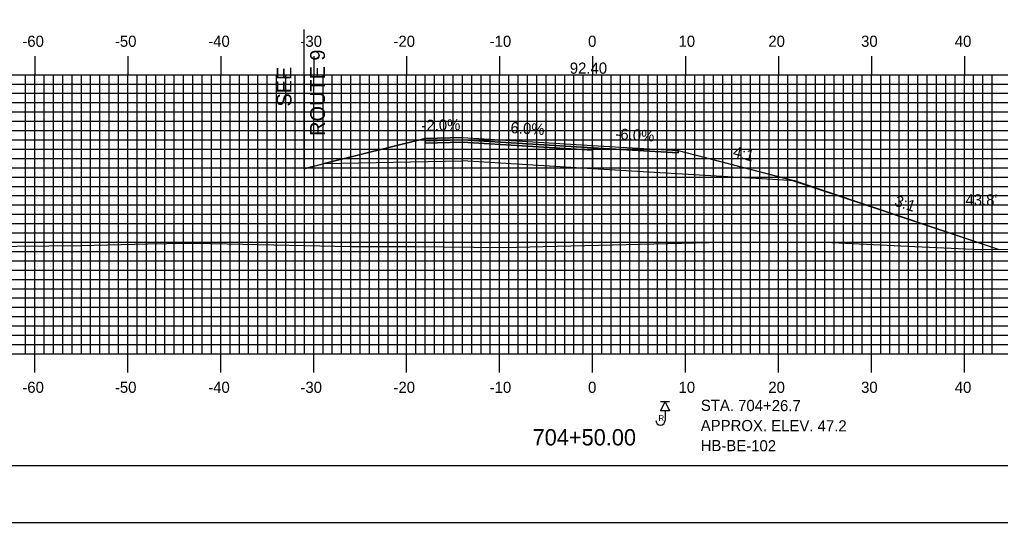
# Model space of a CAD drawing. Extents: x 853723 to 854066, y 364366 to 364586.
# Drawn here: x 853827.1 to 853932.6, y 364365.7 to 364419.7 of the extents above; entities that cross this region are included whole.
import ezdxf

# ---------------------------------------------------------------- set-up
doc = ezdxf.new("R2010")
doc.units = 0
for name, color, linetype in [('ANNOTATION', 7, 'Continuous'), ('BORDER', 7, 'Continuous'), ('BORING - REFUSAL', 7, 'Continuous'), ('D_Roadway_Centerline', 7, 'Continuous'), ('D_Roadway_Centerline_Text', 7, 'Continuous'), ('D_Roadway_Edge_Shoulder', 7, 'Continuous'), ('D_Roadway_Edge_TW', 7, 'Continuous'), ('D_Roadway_Pavement', 7, 'Continuous'), ('D_Roadway_SlopeLines', 7, 'Continuous'), ('D_Roadway_SubGrade', 7, 'Continuous'), ('D_Text_Standard', 7, 'Continuous'), ('H_V ANNOTATION', 7, 'Continuous'), ('MAJOR', 7, 'Continuous'), ('MINOR', 7, 'Continuous'), ('PLOT BOUNDARY', 7, 'Continuous'), ('S_Roadway_Centerline', 7, 'Continuous')]:
    doc.layers.add(name, color=color, linetype=linetype)

msp = doc.modelspace()

# ---------------------------------------------------------------- linework, layer by layer
at = {"layer": 'BORDER'}
msp.add_lwpolyline([(853739.12, 364371.79), (854059.12, 364371.79), (854059.12, 364581.79), (853739.12, 364581.79)], close=True, dxfattribs=at)
at = {"layer": 'BORING - REFUSAL'}
for p, q in [((853897, 364378.63), (853896.04, 364378.63)), ((853896.52, 364377.67), (853896.52, 364376.61))]:
    msp.add_line(p, q, dxfattribs=at)
msp.add_lwpolyline([(853896.52, 364378.63), (853897, 364377.67), (853896.04, 364377.67)], close=True, dxfattribs=at)
msp.add_arc((853896.03, 364376.61), 0.485, 180, 0, dxfattribs=at)
at = {"layer": 'D_Roadway_Centerline'}
msp.add_lwpolyline([(853857.67, 364403.69), (853859.85, 364404.23), (853870.72, 364406.95), (853874.72, 364407.03), (853888.72, 364406.19), (853897.92, 364405.64), (853909.92, 364402.54), (853910.52, 364402.38), (853932.48, 364395.02)], dxfattribs=at)
at = {"layer": 'D_Roadway_Edge_Shoulder'}
for points in [[(853874.72, 364407.03), (853870.72, 364406.95), (853870.72, 364406.7), (853874.72, 364406.78)], [(853888.72, 364406.19), (853897.92, 364405.64), (853897.92, 364405.39), (853888.72, 364405.94)]]:
    msp.add_lwpolyline(points, close=True, dxfattribs=at)
at = {"layer": 'D_Roadway_Edge_TW'}
msp.add_lwpolyline([(853874.72, 364407.03), (853888.72, 364406.19), (853888.72, 364405.94), (853874.72, 364406.78)], close=True, dxfattribs=at)
at = {"layer": 'D_Roadway_Pavement'}
for points in [[(853874.72, 364406.78), (853870.72, 364406.7), (853870.72, 364406.45), (853874.72, 364406.53)], [(853874.72, 364406.78), (853888.72, 364405.94), (853888.72, 364405.69), (853874.72, 364406.53)]]:
    msp.add_lwpolyline(points, close=True, dxfattribs=at)
msp.add_lwpolyline([(853888.72, 364405.94), (853888.72, 364405.69)], dxfattribs=at)
msp.add_lwpolyline([(853888.72, 364405.94), (853888.72, 364405.69)], dxfattribs=at)
at = {"layer": 'D_Roadway_SlopeLines'}
for points in [[(853870.72, 364406.95), (853857.67, 364403.69)], [(853897.92, 364405.64), (853909.92, 364402.54), (853932.48, 364395.02)]]:
    msp.add_lwpolyline(points, dxfattribs=at)
at = {"layer": 'D_Roadway_SubGrade'}
msp.add_line((853857.67, 364418.64), (853857.67, 364403.69), dxfattribs=at)
for points in [[(853874.72, 364406.53), (853870.72, 364406.45), (853870.72, 364406.7), (853870.72, 364406.95), (853859.85, 364404.23), (853874.72, 364404.53)], [(853874.72, 364406.53), (853888.72, 364405.69), (853888.72, 364403.69), (853874.72, 364404.53)], [(853888.72, 364405.69), (853888.72, 364405.94), (853897.92, 364405.39), (853897.92, 364405.64), (853910.52, 364402.38), (853888.72, 364403.69)]]:
    msp.add_lwpolyline(points, close=True, dxfattribs=at)
at = {"layer": 'MAJOR'}
for p, q in [((853828.72, 364415.79), (853828.72, 364413.79)), ((853838.72, 364415.79), (853838.72, 364413.79)), ((853848.72, 364415.79), (853848.72, 364413.79)), ((853858.72, 364415.79), (853858.72, 364413.79)), ((853868.72, 364415.79), (853868.72, 364413.79)), ((853878.72, 364415.79), (853878.72, 364413.79)), ((853888.72, 364415.79), (853888.72, 364413.79)), ((853898.72, 364415.79), (853898.72, 364413.79)), ((853908.72, 364415.79), (853908.72, 364413.79)), ((853918.72, 364415.79), (853918.72, 364413.79)), ((853928.72, 364415.79), (853928.72, 364413.79)), ((853748.72, 364413.79), (854028.72, 364413.79)), ((853748.72, 364413.79), (854028.72, 364413.79)), ((853828.72, 364383.79), (853828.72, 364413.79)), ((853838.72, 364383.79), (853838.72, 364413.79)), ((853848.72, 364383.79), (853848.72, 364413.79)), ((853858.72, 364383.79), (853858.72, 364413.79)), ((853868.72, 364383.79), (853868.72, 364413.79)), ((853878.72, 364383.79), (853878.72, 364413.79)), ((853888.72, 364383.79), (853888.72, 364413.79)), ((853898.72, 364383.79), (853898.72, 364413.79)), ((853908.72, 364383.79), (853908.72, 364413.79)), ((853918.72, 364383.79), (853918.72, 364413.79)), ((853928.72, 364383.79), (853928.72, 364413.79)), ((853748.72, 364408.79), (854028.72, 364408.79)), ((853748.72, 364403.79), (854028.72, 364403.79)), ((853748.72, 364398.79), (854028.72, 364398.79)), ((853748.72, 364393.79), (854028.72, 364393.79)), ((853748.72, 364388.79), (854028.72, 364388.79)), ((853748.72, 364383.79), (854028.72, 364383.79)), ((853748.72, 364383.79), (854028.72, 364383.79)), ((853828.72, 364381.78), (853828.72, 364383.79)), ((853838.72, 364381.78), (853838.72, 364383.79)), ((853848.72, 364381.78), (853848.72, 364383.79)), ((853858.72, 364381.78), (853858.72, 364383.79)), ((853868.72, 364381.78), (853868.72, 364383.79)), ((853878.72, 364381.78), (853878.72, 364383.79)), ((853888.72, 364381.78), (853888.72, 364383.79)), ((853898.72, 364381.78), (853898.72, 364383.79)), ((853908.72, 364381.78), (853908.72, 364383.79)), ((853918.72, 364381.78), (853918.72, 364383.79)), ((853928.72, 364381.78), (853928.72, 364383.79))]:
    msp.add_line(p, q, dxfattribs=at)
at = {"layer": 'MINOR'}
for p, q in [((853827.72, 364383.79), (853827.72, 364413.79)), ((853829.72, 364383.79), (853829.72, 364413.79)), ((853830.72, 364383.79), (853830.72, 364413.79)), ((853831.72, 364383.79), (853831.72, 364413.79)), ((853832.72, 364383.79), (853832.72, 364413.79)), ((853833.72, 364383.79), (853833.72, 364413.79)), ((853834.72, 364383.79), (853834.72, 364413.79)), ((853835.72, 364383.79), (853835.72, 364413.79)), ((853836.72, 364383.79), (853836.72, 364413.79)), ((853837.72, 364383.79), (853837.72, 364413.79)), ((853839.72, 364383.79), (853839.72, 364413.79)), ((853840.72, 364383.79), (853840.72, 364413.79)), ((853841.72, 364383.79), (853841.72, 364413.79)), ((853842.72, 364383.79), (853842.72, 364413.79)), ((853843.72, 364383.79), (853843.72, 364413.79)), ((853844.72, 364383.79), (853844.72, 364413.79)), ((853845.72, 364383.79), (853845.72, 364413.79)), ((853846.72, 364383.79), (853846.72, 364413.79)), ((853847.72, 364383.79), (853847.72, 364413.79)), ((853849.72, 364383.79), (853849.72, 364413.79)), ((853850.72, 364383.79), (853850.72, 364413.79)), ((853851.72, 364383.79), (853851.72, 364413.79)), ((853852.72, 364383.79), (853852.72, 364413.79)), ((853853.72, 364383.79), (853853.72, 364413.79)), ((853854.72, 364383.79), (853854.72, 364413.79)), ((853855.72, 364383.79), (853855.72, 364413.79)), ((853856.72, 364383.79), (853856.72, 364413.79)), ((853857.72, 364383.79), (853857.72, 364413.79)), ((853859.72, 364383.79), (853859.72, 364413.79)), ((853860.72, 364383.79), (853860.72, 364413.79)), ((853861.72, 364383.79), (853861.72, 364413.79)), ((853862.72, 364383.79), (853862.72, 364413.79)), ((853863.72, 364383.79), (853863.72, 364413.79)), ((853864.72, 364383.79), (853864.72, 364413.79)), ((853865.72, 364383.79), (853865.72, 364413.79)), ((853866.72, 364383.79), (853866.72, 364413.79)), ((853867.72, 364383.79), (853867.72, 364413.79)), ((853869.72, 364383.79), (853869.72, 364413.79)), ((853870.72, 364383.79), (853870.72, 364413.79)), ((853871.72, 364383.79), (853871.72, 364413.79)), ((853872.72, 364383.79), (853872.72, 364413.79)), ((853873.72, 364383.79), (853873.72, 364413.79)), ((853874.72, 364383.79), (853874.72, 364413.79)), ((853875.72, 364383.79), (853875.72, 364413.79)), ((853876.72, 364383.79), (853876.72, 364413.79)), ((853877.72, 364383.79), (853877.72, 364413.79)), ((853879.72, 364383.79), (853879.72, 364413.79)), ((853880.72, 364383.79), (853880.72, 364413.79)), ((853881.72, 364383.79), (853881.72, 364413.79)), ((853882.72, 364383.79), (853882.72, 364413.79)), ((853883.72, 364383.79), (853883.72, 364413.79)), ((853884.72, 364383.79), (853884.72, 364413.79)), ((853885.72, 364383.79), (853885.72, 364413.79)), ((853886.72, 364383.79), (853886.72, 364413.79)), ((853887.72, 364383.79), (853887.72, 364413.79)), ((853889.72, 364383.79), (853889.72, 364413.79)), ((853890.72, 364383.79), (853890.72, 364413.79)), ((853891.72, 364383.79), (853891.72, 364413.79)), ((853892.72, 364383.79), (853892.72, 364413.79)), ((853893.72, 364383.79), (853893.72, 364413.79)), ((853894.72, 364383.79), (853894.72, 364413.79)), ((853895.72, 364383.79), (853895.72, 364413.79)), ((853896.72, 364383.79), (853896.72, 364413.79)), ((853897.72, 364383.79), (853897.72, 364413.79)), ((853899.72, 364383.79), (853899.72, 364413.79)), ((853900.72, 364383.79), (853900.72, 364413.79)), ((853901.72, 364383.79), (853901.72, 364413.79)), ((853902.72, 364383.79), (853902.72, 364413.79)), ((853903.72, 364383.79), (853903.72, 364413.79)), ((853904.72, 364383.79), (853904.72, 364413.79)), ((853905.72, 364383.79), (853905.72, 364413.79)), ((853906.72, 364383.79), (853906.72, 364413.79)), ((853907.72, 364383.79), (853907.72, 364413.79)), ((853909.72, 364383.79), (853909.72, 364413.79)), ((853910.72, 364383.79), (853910.72, 364413.79)), ((853911.72, 364383.79), (853911.72, 364413.79)), ((853912.72, 364383.79), (853912.72, 364413.79)), ((853913.72, 364383.79), (853913.72, 364413.79)), ((853914.72, 364383.79), (853914.72, 364413.79)), ((853915.72, 364383.79), (853915.72, 364413.79)), ((853916.72, 364383.79), (853916.72, 364413.79)), ((853917.72, 364383.79), (853917.72, 364413.79)), ((853919.72, 364383.79), (853919.72, 364413.79)), ((853920.72, 364383.79), (853920.72, 364413.79)), ((853921.72, 364383.79), (853921.72, 364413.79)), ((853922.72, 364383.79), (853922.72, 364413.79)), ((853923.72, 364383.79), (853923.72, 364413.79)), ((853924.72, 364383.79), (853924.72, 364413.79)), ((853925.72, 364383.79), (853925.72, 364413.79)), ((853926.72, 364383.79), (853926.72, 364413.79)), ((853927.72, 364383.79), (853927.72, 364413.79)), ((853929.72, 364383.79), (853929.72, 364413.79)), ((853930.72, 364383.79), (853930.72, 364413.79)), ((853931.72, 364383.79), (853931.72, 364413.79)), ((853748.72, 364412.79), (854028.72, 364412.79)), ((853748.72, 364411.79), (854028.72, 364411.79)), ((853748.72, 364410.79), (854028.72, 364410.79)), ((853748.72, 364409.79), (854028.72, 364409.79)), ((853748.72, 364407.79), (854028.72, 364407.79)), ((853748.72, 364406.79), (854028.72, 364406.79)), ((853748.72, 364405.79), (854028.72, 364405.79)), ((853748.72, 364404.79), (854028.72, 364404.79)), ((853748.72, 364402.79), (854028.72, 364402.79)), ((853748.72, 364401.79), (854028.72, 364401.79)), ((853748.72, 364400.79), (854028.72, 364400.79)), ((853748.72, 364399.79), (854028.72, 364399.79)), ((853748.72, 364397.79), (854028.72, 364397.79)), ((853748.72, 364396.79), (854028.72, 364396.79)), ((853748.72, 364395.79), (854028.72, 364395.79)), ((853748.72, 364394.79), (854028.72, 364394.79)), ((853748.72, 364392.79), (854028.72, 364392.79)), ((853748.72, 364391.79), (854028.72, 364391.79)), ((853748.72, 364390.79), (854028.72, 364390.79)), ((853748.72, 364389.79), (854028.72, 364389.79)), ((853748.72, 364387.79), (854028.72, 364387.79)), ((853748.72, 364386.79), (854028.72, 364386.79)), ((853748.72, 364385.79), (854028.72, 364385.79)), ((853748.72, 364384.79), (854028.72, 364384.79))]:
    msp.add_line(p, q, dxfattribs=at)
at = {"layer": 'PLOT BOUNDARY'}
msp.add_lwpolyline([(853722.93, 364365.67), (854062.93, 364365.67), (854062.93, 364585.67), (853722.93, 364585.67)], close=True, dxfattribs=at)
at = {"layer": 'S_Roadway_Centerline'}
msp.add_lwpolyline([(853748.72, 364394.6), (853760.71, 364394.72), (853768.68, 364394.72), (853777.15, 364394.69), (853789.37, 364394.86), (853793.33, 364394.92), (853801.44, 364395.04), (853810.89, 364395.05), (853816.39, 364395.26), (853833.68, 364395.44), (853840.88, 364395.6), (853844.96, 364395.68), (853845.88, 364395.69), (853849.46, 364395.62), (853862.69, 364395.31), (853869.61, 364395.32), (853879.11, 364395.2), (853883.39, 364395.34), (853902.78, 364395.79), (853910.05, 364395.81), (853913.72, 364395.8), (853923.38, 364395.33), (853930.43, 364395), (853940.64, 364395.08)], dxfattribs=at)

# ---------------------------------------------------------------- texts
at = {"layer": 'ANNOTATION'}
for s, height, rotation, p in [('ROUTE 9', 1.6, 90, (853859.93, 364407.22)), ('SEE', 1.6, 90, (853856.33, 364410.37)), ('-2.0%', 1.2, 1.1458, (853870.32, 364407.74)), ('6.0%', 1.2, 356.5664, (853879.87, 364407.52)), ('-6.0%', 1.2, 356.5664, (853891.15, 364406.85)), ('4:1', 1.2, 345.5153, (853903.74, 364405)), ('3:1', 1.2, 341.4587, (853921.11, 364399.74))]:
    msp.add_text(s, height=height, rotation=rotation, dxfattribs=at).set_placement(p)
at = {"layer": 'BORING - REFUSAL'}
for s, p in [('STA. 704+26.7', (853900.37, 364377.65)), ('APPROX. ELEV. 47.2', (853900.36, 364375.49)), ('HB-BE-102', (853900.35, 364373.33))]:
    msp.add_text(s, height=1.2, rotation=359.8142, dxfattribs=at).set_placement(p)
msp.add_text('R', height=0.64, dxfattribs=at).set_placement((853895.81, 364376.56))
at = {"layer": 'D_Roadway_Centerline_Text'}
msp.add_text('92.40', height=1.2, dxfattribs=at).set_placement((853886.27, 364413.9))
at = {"layer": 'D_Text_Standard'}
msp.add_text("43.8'", height=1.2, dxfattribs=at).set_placement((853928.84, 364399.74))
at = {"layer": 'H_V ANNOTATION'}
for s, height, p in [('-60', 1.2, (853827.37, 364416.79)), ('-50', 1.2, (853837.33, 364416.79)), ('-40', 1.2, (853847.37, 364416.79)), ('-30', 1.2, (853857.29, 364416.79)), ('-20', 1.2, (853867.3, 364416.79)), ('-10', 1.2, (853877.65, 364416.79)), ('0', 1.2, (853888.24, 364416.79)), ('10', 1.2, (853897.97, 364416.79)), ('20', 1.2, (853907.63, 364416.79)), ('30', 1.2, (853917.61, 364416.79)), ('40', 1.2, (853927.69, 364416.79)), ('-60', 1.2, (853827.37, 364379.59)), ('-50', 1.2, (853837.33, 364379.59)), ('-40', 1.2, (853847.37, 364379.59)), ('-30', 1.2, (853857.29, 364379.59)), ('-20', 1.2, (853867.3, 364379.59)), ('-10', 1.2, (853877.65, 364379.59)), ('0', 1.2, (853888.24, 364379.59)), ('10', 1.2, (853897.97, 364379.59)), ('20', 1.2, (853907.63, 364379.59)), ('30', 1.2, (853917.61, 364379.59)), ('40', 1.2, (853927.69, 364379.59)), ('704+50.00', 1.75, (853882.27, 364373.94))]:
    msp.add_text(s, height=height, dxfattribs=at).set_placement(p)

doc.saveas('drawing.dxf')
